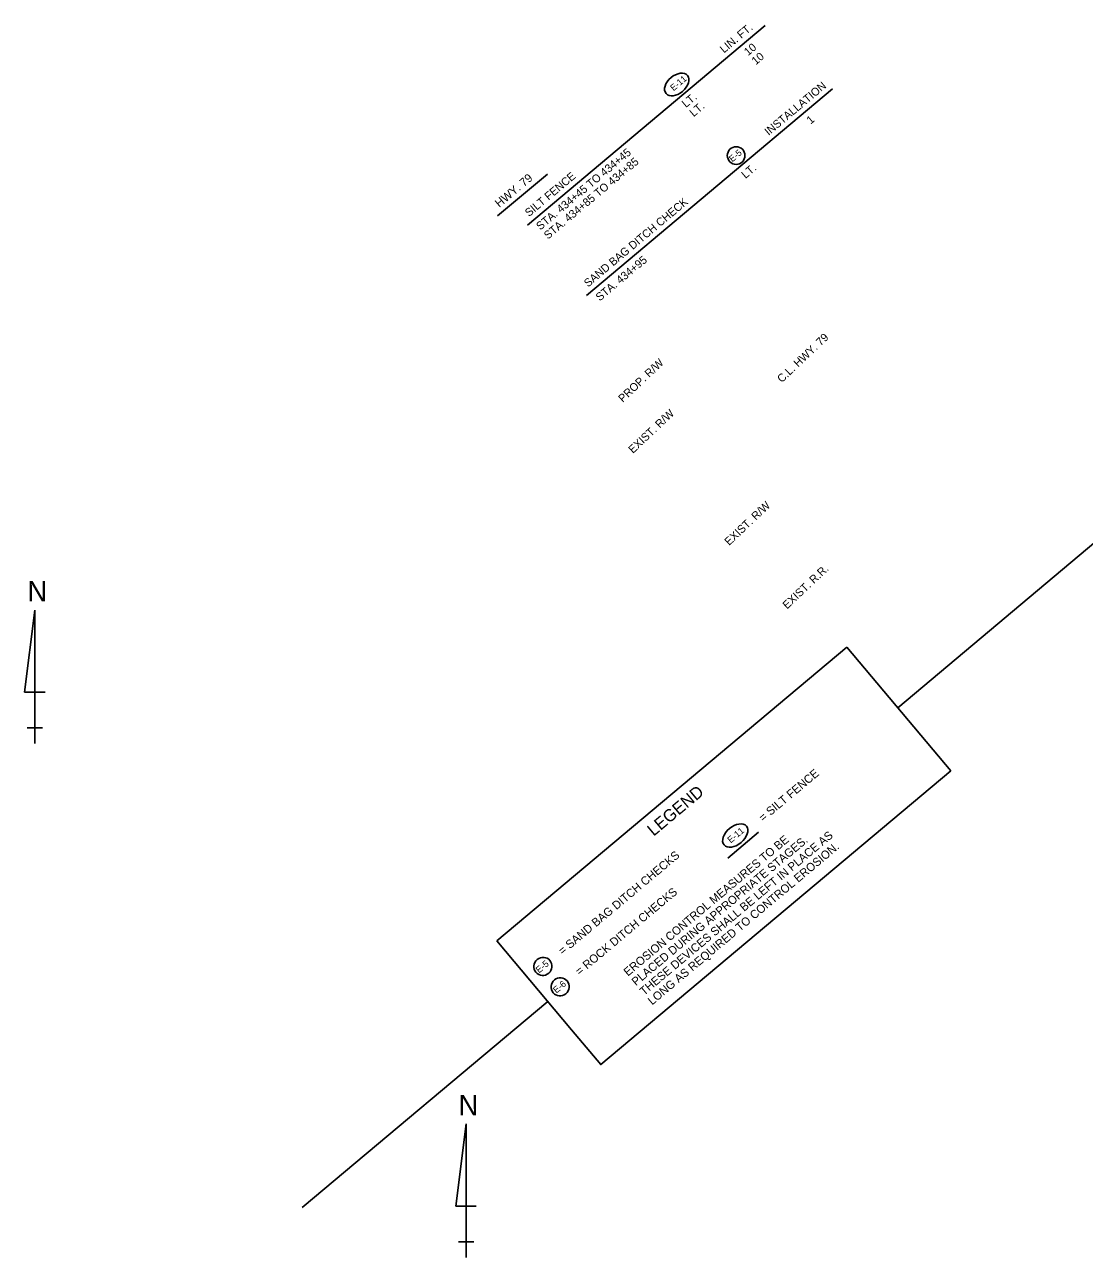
# Model space of a CAD drawing. Extents: x 1430270 to 1431940, y 1964864 to 1966264.
# Drawn here: x 1430270 to 1431064, y 1964864 to 1965788 of the extents above; entities that cross this region are included whole.
import ezdxf

# ---------------------------------------------------------------- set-up
doc = ezdxf.new("R2010")
doc.units = 0
for name, color, linetype in [('1', 7, 'Continuous'), ('44', 7, 'Continuous'), ('63', 7, 'Continuous'), ('Level 1', 7, 'Continuous'), ('Level 44', 7, 'Continuous'), ('R_Draft', 7, 'Continuous')]:
    doc.layers.add(name, color=color, linetype=linetype)

msp = doc.modelspace()

# ---------------------------------------------------------------- linework, layer by layer
at = {"layer": '1'}
for p, q in [((1430924.55, 1965276.13), (1431143.78, 1965460.09)), ((1430623.95, 1965101.3), (1430886.44, 1965321.55)), ((1430964.25, 1965228.82), (1430886.44, 1965321.55)), ((1430679.95, 1965034.55), (1430623.95, 1965101.3)), ((1430477.81, 1964901.27), (1430662.06, 1965055.88))]:
    msp.add_line(p, q, dxfattribs=at)
msp.add_lwpolyline([(1430679.95, 1965034.55), (1430701.76, 1965008.57), (1430964.25, 1965228.82)], dxfattribs=at)
msp.add_circle((1430803.32, 1965690.19), 6.61, dxfattribs=at)
msp.add_ellipse((1430758.79, 1965743.46), major_axis=(8.06, 6.76), ratio=0.638788, dxfattribs=at)
at = {"layer": '44'}
for p, q in [((1430646.71, 1965638.03), (1430825.04, 1965787.67)), ((1430691.02, 1965585.22), (1430875.64, 1965740.14)), ((1430624.4, 1965644.89), (1430661.81, 1965676.28))]:
    msp.add_line(p, q, dxfattribs=at)
at = {"layer": '63'}
for p, q in [((1430277.36, 1965349.41), (1430269.66, 1965287.87)), ((1430277.36, 1965249.41), (1430277.36, 1965349.41)), ((1430277.36, 1965349.41), (1430277.36, 1965272.49)), ((1430269.66, 1965287.87), (1430285.05, 1965287.87)), ((1430277.36, 1965249.41), (1430277.36, 1965272.49)), ((1430277.36, 1965260.95), (1430271.59, 1965260.95)), ((1430271.59, 1965260.95), (1430283.13, 1965260.95)), ((1430277.36, 1965249.41), (1430277.36, 1965260.95)), ((1430600.76, 1964963.99), (1430593.06, 1964902.46)), ((1430600.76, 1964863.99), (1430600.76, 1964963.99)), ((1430600.76, 1964963.99), (1430600.76, 1964887.07)), ((1430593.06, 1964902.46), (1430608.45, 1964902.46)), ((1430600.76, 1964863.99), (1430600.76, 1964887.07)), ((1430600.76, 1964875.53), (1430594.99, 1964875.53)), ((1430594.99, 1964875.53), (1430606.53, 1964875.53)), ((1430600.76, 1964863.99), (1430600.76, 1964875.53))]:
    msp.add_line(p, q, dxfattribs=at)
at = {"layer": 'Level 1'}
for centre, major_axis, ratio in [((1430802.63, 1965180.25), (8.39, 7.04), 0.622952), ((1430658.42, 1965082.15), (-5.27, -4.42), 0.97521), ((1430671.28, 1965066.83), (-5.27, -4.42), 0.97521)]:
    msp.add_ellipse(centre, major_axis=major_axis, ratio=ratio, dxfattribs=at)
at = {"layer": 'Level 44'}
msp.add_lwpolyline([(1430797.09, 1965163.42), (1430820.16, 1965182.79)], dxfattribs=at)

# ---------------------------------------------------------------- texts
at = {"layer": '1'}
for s, rotation, p in [('E-11', 39.99998, (1430756.33, 1965738.31)), ('E-5 ', 40, (1430800.45, 1965685.06))]:
    msp.add_text(s, height=4.8, rotation=rotation, dxfattribs=at).set_placement(p)
at = {"layer": '44'}
for s, height, rotation, p in [('LIN. FT.', 6, 39.99998, (1430794.17, 1965766.67)), ('10', 6, 39.99998, (1430812.29, 1965764.67)), ('10', 6, 39.99998, (1430818.04, 1965757.82)), ('INSTALLATION', 6, 40, (1430827.76, 1965704.86)), ('LT.', 6, 39.99998, (1430765.65, 1965725.75)), ('LT.', 6, 39.99998, (1430771.41, 1965718.9)), ('1', 6, 40, (1430859.2, 1965713.37)), ('STA. 434+45 TO 434+45', 6, 39.99998, (1430656.42, 1965633.91)), ('STA. 434+85 TO 434+85', 6, 39.99998, (1430662.18, 1965627.05)), ('HWY. 79', 6.25, 40, (1430625.68, 1965650.9)), ('SILT FENCE      ', 6, 39.99998, (1430647.97, 1965643.99)), ('LT.', 6, 40, (1430810.3, 1965672.55)), ('SAND BAG DITCH CHECK', 6, 40, (1430692.28, 1965591.18)), ('STA. 434+95', 6, 40, (1430701.07, 1965580.71))]:
    msp.add_text(s, height=height, rotation=rotation, dxfattribs=at).set_placement(p)
at = {"layer": '63'}
for p in [(1430271.72, 1965355.82), (1430595.12, 1964970.4)]:
    msp.add_text('N', height=15.38, rotation=360, dxfattribs=at).set_placement(p)
at = {"layer": 'Level 1'}
for s, height, p in [('= SILT FENCE', 6.25, (1430823.53, 1965190.25)), ('E-11 ', 4.876, (1430799.27, 1965174.31)), ('EROSION CONTROL MEASURES TO BE', 6.25, (1430722.15, 1965074.45)), ('PLACED DURING APPROPRIATE STAGES. ', 6.25, (1430728.2, 1965067.24)), ('THESE DEVICES SHALL BE LEFT IN PLACE AS ', 6.25, (1430734.25, 1965060.03)), ('= SAND BAG DITCH CHECKS', 6.25, (1430673.09, 1965090.38)), ('LONG AS REQUIRED TO CONTROL EROSION.', 6.25, (1430740.3, 1965052.83)), ('= ROCK DITCH CHECKS', 6.25, (1430685.95, 1965075.06)), ('E-5 ', 4.876, (1430655.53, 1965076.83)), ('E-6 ', 4.876, (1430668.49, 1965061.71))]:
    msp.add_text(s, height=height, rotation=40.00001, dxfattribs=at).set_placement(p)
at = {"layer": 'Level 44'}
msp.add_text('LEGEND', height=9.143, rotation=40.00001, dxfattribs=at).set_placement((1430741.39, 1965179.35))
at = {"layer": 'R_Draft'}
for s, rotation, p in [('C.L. HWY. 79', 43.42441, (1430837.55, 1965519.46)), ('PROP. R/W', 43.36601, (1430718.35, 1965504.7)), ('EXIST. R/W', 43.36601, (1430725.92, 1965466.42)), ('EXIST. R/W', 43.36601, (1430798.03, 1965397.38)), ('EXIST. R.R.', 43.39194, (1430841.54, 1965349.75))]:
    msp.add_text(s, height=6, rotation=rotation, dxfattribs=at).set_placement(p)

doc.saveas('drawing.dxf')
